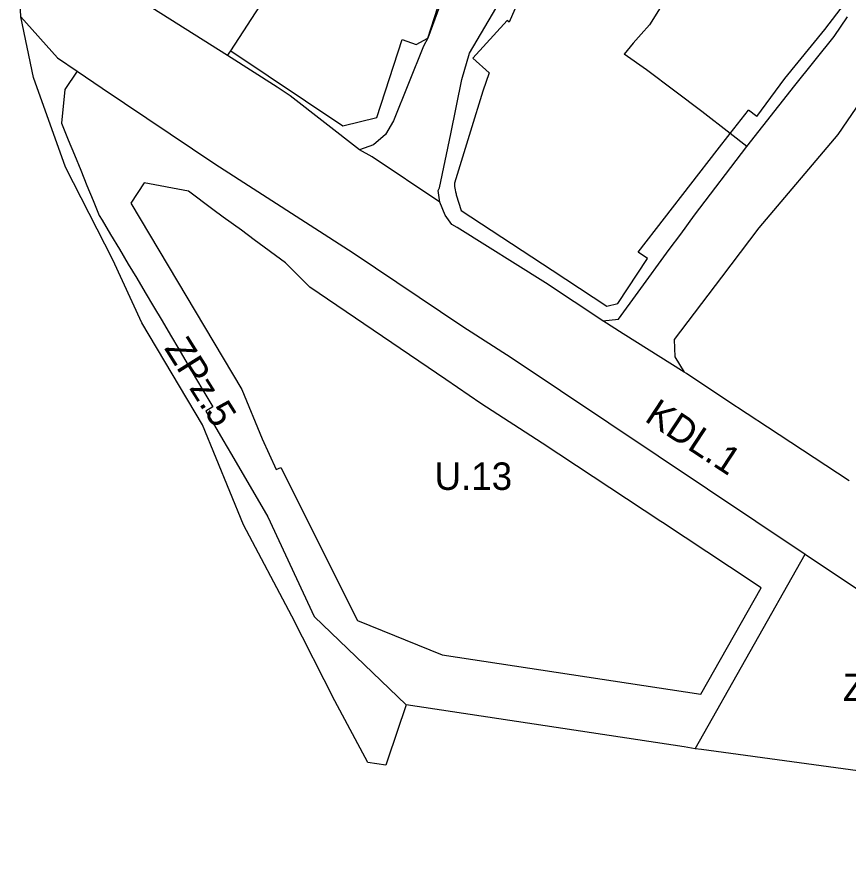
# Model space of a CAD drawing. Extents: x 7425067 to 7426806, y 5549054 to 5550619.
# Drawn here: x 7425296.9 to 7425448.3, y 5549793.4 to 5549946.2 of the extents above; entities that cross this region are included whole.
import ezdxf

# ---------------------------------------------------------------- set-up
doc = ezdxf.new("R2010")
doc.units = 0
for name, color, linetype in [('LIN_Linia Zabudowy Nieprzekraczalna', 7, 'Continuous'), ('LIN_linie_rozgraniczajace', 7, 'Continuous'), ('TXT_Oznaczenia_przeznaczen', 7, 'Continuous')]:
    doc.layers.add(name, color=color, linetype=linetype)

msp = doc.modelspace()

# ---------------------------------------------------------------- linework, layer by layer
at = {"layer": 'LIN_Linia Zabudowy Nieprzekraczalna'}
for points in [[(7425367.1006, 5549942.0677), (7425369.63, 5549941.18), (7425371.78, 5549942.28), (7425375.41, 5549953.64), (7425379.09, 5549962.5), (7425383.52, 5549973.76), (7425392.98, 5549990.68), (7425396.6, 5549997.31), (7425402.98, 5550008.69), (7425404.23, 5550011.01), (7425410.43, 5550022.22), (7425411.71, 5550024.85), (7425415.09, 5550030.67), (7425418.41, 5550036.6), (7425425.3797, 5550049.1825)], [(7425398.7566, 5549968.6855), (7425398.6261, 5549968.5893), (7425398.5769, 5549968.5036), (7425393.6834, 5549959.6655), (7425389.9392, 5549952.5103), (7425389.1819, 5549951.2183), (7425388.8947, 5549950.5772), (7425386.5508, 5549945.2404), (7425386.22, 5549945.54), (7425379.98, 5549938.66), (7425382.9229, 5549935.9972), (7425381.7632, 5549932.624)], [(7425431.7, 5549928.06), (7425436.81, 5549934.94), (7425444.07, 5549943.88), (7425449.03, 5549950.47), (7425451.65, 5549953.86), (7425452.01, 5549953.65), (7425452.67, 5549953.77), (7425454.76, 5549956.39), (7425454.96, 5549957.03), (7425454.71, 5549957.65), (7425456.96, 5549961.01), (7425462.62, 5549968.26)], [(7425356.2749, 5549926.3541), (7425362.4532, 5549927.8264), (7425367.1006, 5549942.0677)], [(7425335.8824, 5549940.0045), (7425356.2749, 5549926.3541)], [(7425381.7632, 5549932.624), (7425379.5164, 5549925.391), (7425376.6467, 5549915.9092), (7425376.6178, 5549915.7649), (7425376.6095, 5549915.7056), (7425376.6027, 5549915.5671), (7425376.6048, 5549915.4495), (7425376.6186, 5549915.3051), (7425376.7518, 5549914.6797), (7425376.821, 5549914.2822), (7425376.9036, 5549913.9309), (7425376.9472, 5549913.782), (7425377.81, 5549910.93)], [(7425410.0653, 5549903.2949), (7425424.48, 5549921.87), (7425426.8506, 5549924.9248), (7425430.1714, 5549929.2041)], [(7425431.7, 5549928.06), (7425430.1714, 5549929.2041)], [(7425320.1079, 5549915.9425), (7425317.67, 5549912.24), (7425337.92, 5549878.29), (7425341.6, 5549869.29), (7425344.14, 5549863.69), (7425345.0178, 5549864.0877), (7425358.95, 5549836.21), (7425374.3959, 5549829.9732), (7425421.4777, 5549822.8114)], [(7425432.4452, 5549842.1639), (7425426.723, 5549845.9762), (7425414.5144, 5549854.036), (7425414.1863, 5549854.2411), (7425392.6156, 5549868.5413), (7425381.4138, 5549875.7712), (7425375.0267, 5549880.1422), (7425350.27, 5549896.96), (7425345.83, 5549901.4), (7425340.17, 5549905.57), (7425337.81, 5549907.33), (7425334.49, 5549909.71), (7425332.62, 5549911.09), (7425328.16, 5549914.42), (7425320.1079, 5549915.9425)], [(7425377.81, 5549910.93), (7425394.43, 5549900.06), (7425404.36, 5549893.46), (7425406.39, 5549893.97), (7425411.78, 5549902.16), (7425410.0653, 5549903.2949)], [(7425421.4777, 5549822.8114), (7425432.4452, 5549842.1639)]]:
    msp.add_lwpolyline(points, dxfattribs=at)
at = {"layer": 'LIN_linie_rozgraniczajace'}
for points in [[(7425297.65, 5549946.19), (7425296.91, 5549961.35)], [(7425335.31, 5549939.12), (7425311.01, 5549954.5)], [(7425335.31, 5549939.12), (7425335.8824, 5549940.0045), (7425344.995, 5549954.085)], [(7425373.88, 5549948.075), (7425371.78, 5549942.28), (7425370.99, 5549940.85)], [(7425379.36, 5549939.6), (7425384.91, 5549949.07)], [(7425414.065, 5549947.82), (7425412.11, 5549944.71)], [(7425297.65, 5549946.19), (7425304.34, 5549938.72)], [(7425299.98, 5549935.11), (7425297.65, 5549946.19)], [(7425445.78, 5549942.63), (7425448.18, 5549946.22)], [(7425412.11, 5549944.71), (7425410.63, 5549943.04)], [(7425410.63, 5549943.04), (7425409.15, 5549941.37)], [(7425438.58, 5549933.68), (7425445.78, 5549942.63)], [(7425459.01, 5549943.13), (7425446.415, 5549924.73)], [(7425370.99, 5549940.85), (7425365.53, 5549927.24)], [(7425409.15, 5549941.37), (7425407.52, 5549939.41)], [(7425344.35, 5549933.36), (7425335.31, 5549939.12)], [(7425377.96, 5549934.76), (7425379.36, 5549939.6)], [(7425429.87, 5549922.58), (7425426.8506, 5549924.9248), (7425421.68, 5549928.94), (7425416.76, 5549932.65), (7425411.6, 5549936.56), (7425407.52, 5549939.41)], [(7425304.34, 5549938.72), (7425307.9, 5549936.29)], [(7425307.9, 5549936.29), (7425305.67, 5549932.97)], [(7425307.9, 5549936.29), (7425312.44, 5549933.19)], [(7425305.76, 5549918.78), (7425299.98, 5549935.11)], [(7425375.93, 5549924.905), (7425377.96, 5549934.76)], [(7425305.67, 5549932.97), (7425305.05, 5549926.79)], [(7425312.44, 5549933.19), (7425332.98, 5549919.44)], [(7425346.72, 5549931.8), (7425344.35, 5549933.36)], [(7425429.87, 5549922.58), (7425438.58, 5549933.68)], [(7425359.3, 5549921.97), (7425346.72, 5549931.8)], [(7425305.05, 5549926.79), (7425306.28, 5549923.79)], [(7425365.53, 5549927.24), (7425364.04, 5549924.75)], [(7425306.28, 5549923.79), (7425307.41, 5549921.02)], [(7425364.04, 5549924.75), (7425361.87, 5549922.86)], [(7425373.9, 5549915.05), (7425375.93, 5549924.905)], [(7425446.415, 5549924.73), (7425432.05, 5549907.72)], [(7425361.87, 5549922.86), (7425359.3, 5549921.97)], [(7425361.65, 5549920.67), (7425359.3, 5549921.97)], [(7425420.36, 5549910.05), (7425429.87, 5549922.58)], [(7425307.41, 5549921.02), (7425308.55, 5549918.25)], [(7425373.95, 5549912.44), (7425361.65, 5549920.67)], [(7425332.98, 5549919.44), (7425358.18, 5549903.22)], [(7425314.39, 5549901.91), (7425305.76, 5549918.78)], [(7425308.55, 5549918.25), (7425309.69, 5549915.48)], [(7425309.69, 5549915.48), (7425310.82, 5549912.71)], [(7425373.66, 5549914.53), (7425373.9, 5549915.05)], [(7425373.95, 5549912.44), (7425373.66, 5549914.53)], [(7425310.82, 5549912.71), (7425311.94, 5549909.98)], [(7425374.95, 5549910.08), (7425373.95, 5549912.44)], [(7425311.94, 5549909.98), (7425312.45, 5549909.13)], [(7425376.14, 5549908.33), (7425374.95, 5549910.08)], [(7425417.82, 5549906.61), (7425420.36, 5549910.05)], [(7425312.45, 5549909.13), (7425313.99, 5549906.56)], [(7425377.09, 5549907.81), (7425376.14, 5549908.33)], [(7425393.19, 5549897.75), (7425377.09, 5549907.81)], [(7425432.05, 5549907.72), (7425425.275, 5549898.79)], [(7425313.99, 5549906.56), (7425315.61, 5549903.88)], [(7425415.74, 5549903.805), (7425417.82, 5549906.61)], [(7425315.61, 5549903.88), (7425317.22, 5549901.15)], [(7425410.09, 5549896.05), (7425415.74, 5549903.805)], [(7425358.18, 5549903.22), (7425378.17, 5549889.76)], [(7425319.68, 5549890.47), (7425314.39, 5549901.91)], [(7425317.22, 5549901.15), (7425318.76, 5549898.56)], [(7425318.76, 5549898.56), (7425320.29, 5549895.97)], [(7425403.64, 5549890.8), (7425393.19, 5549897.75)], [(7425425.275, 5549898.79), (7425416.65, 5549887.41)], [(7425320.29, 5549895.97), (7425321.81, 5549893.39)], [(7425406.52, 5549891.1), (7425410.09, 5549896.05)], [(7425321.81, 5549893.39), (7425323.39, 5549890.8)], [(7425330.71, 5549871.85), (7425319.68, 5549890.47)], [(7425323.39, 5549890.8), (7425324.88, 5549888.21)], [(7425403.64, 5549890.8), (7425406.52, 5549891.1)], [(7425407.36, 5549888.45), (7425403.64, 5549890.8)], [(7425378.17, 5549889.76), (7425386.95, 5549884.1)], [(7425418.45, 5549881.45), (7425407.36, 5549888.45)], [(7425324.88, 5549888.21), (7425326.41, 5549885.62)], [(7425416.65, 5549887.41), (7425416.75, 5549884.27)], [(7425326.41, 5549885.62), (7425327.95, 5549883.03)], [(7425386.95, 5549884.1), (7425440.5058, 5549848.2743)], [(7425416.75, 5549884.27), (7425418.45, 5549881.45)], [(7425327.95, 5549883.03), (7425329.47, 5549880.44)], [(7425418.85, 5549881.19), (7425418.45, 5549881.45)], [(7425426.24, 5549876.31), (7425418.85, 5549881.19)], [(7425329.47, 5549880.44), (7425331, 5549877.86)], [(7425331, 5549877.86), (7425332.61, 5549875.16)], [(7425433.63, 5549871.43), (7425426.24, 5549876.31)], [(7425332.61, 5549875.16), (7425331.36, 5549874.36)], [(7425331.36, 5549874.36), (7425332.91, 5549871.74)], [(7425338.21, 5549853.65), (7425330.71, 5549871.85)], [(7425332.91, 5549871.74), (7425334.43, 5549869.14)], [(7425448.47, 5549861.67), (7425433.63, 5549871.43)], [(7425334.43, 5549869.14), (7425336.02, 5549866.45)], [(7425336.02, 5549866.45), (7425342.62, 5549855.07)], [(7425342.62, 5549855.07), (7425351.08, 5549836.93)], [(7425346.99, 5549836.99), (7425338.21, 5549853.65)], [(7425420.43, 5549812.85), (7425440.5058, 5549848.2743)], [(7425440.5058, 5549848.2743), (7425522.4788, 5549793.4392)], [(7425354.82, 5549821.59), (7425346.99, 5549836.99)], [(7425351.08, 5549836.93), (7425367.81, 5549820.86)], [(7425360.83, 5549810.31), (7425354.82, 5549821.59)], [(7425367.81, 5549820.86), (7425364.44, 5549810.78)], [(7425418.43, 5549813.16), (7425367.81, 5549820.86)], [(7425420.43, 5549812.85), (7425418.43, 5549813.16)], [(7425421.63, 5549812.69), (7425420.43, 5549812.85)], [(7425461.2, 5549807.3), (7425421.63, 5549812.69)], [(7425364.44, 5549810.78), (7425364.12, 5549809.83)], [(7425364.12, 5549809.83), (7425360.83, 5549810.31)]]:
    msp.add_lwpolyline(points, dxfattribs=at)

# ---------------------------------------------------------------- texts
at = {"layer": 'TXT_Oznaczenia_przeznaczen'}
for s, rotation, p in [('ZPz.5', 302.147825, (7425323.6699, 5549885.8183)), ('KDL.1', 326.770826, (7425411.0399, 5549872.6645))]:
    msp.add_text(s, height=5, rotation=rotation, dxfattribs=at).set_placement(p)
for s, p in [('U.13', (7425372.9948, 5549860.0009)), ('ZP.1', (7425447.3644, 5549821.522))]:
    msp.add_text(s, height=5, dxfattribs=at).set_placement(p)

doc.saveas('drawing.dxf')
